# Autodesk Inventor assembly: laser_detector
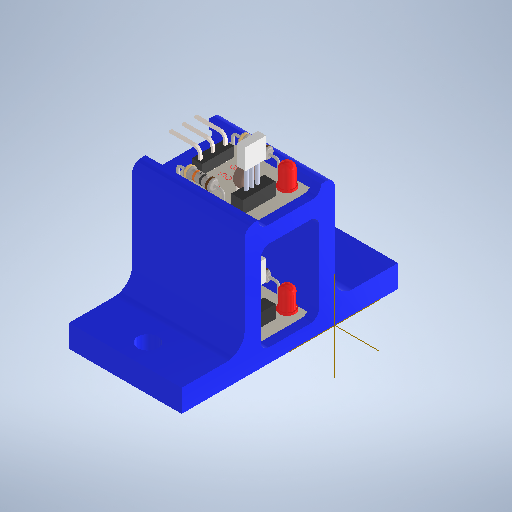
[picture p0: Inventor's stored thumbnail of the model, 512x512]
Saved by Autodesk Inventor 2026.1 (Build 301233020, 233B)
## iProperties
Created: 2026-10
Part Number: laser_detector
Document SubType Name: Assembly
Designer: alolo
Author: alolo
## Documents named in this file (3)
- C:\Users\hp\Documents\Inventor\DOM1_CartesianRobot\laser_detector.iam
- C:\Users\hp\Documents\Inventor\DOM1_CartesianRobot\Laser Detection Hardware.ipt
- C:\Users\hp\Documents\Inventor\DOM1_CartesianRobot\laser_rack.ipt
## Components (3 placed, 2 different names)
1. laser_rack:1 — Mate:1, Mate:2, Mate:3, Mate:4, Mate:5, Mate:6, Mate:7, Mate:8, Mate:9
2. Laser Detection Hardware:1 — Mate:4, Mate:5, Mate:6
3. Laser Detection Hardware:2 — Mate:7, Mate:8, Mate:9
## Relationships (9: Mate 9)
- Mate:1: laser_rack:1
- Mate:2: laser_rack:1
- Mate:3: laser_rack:1
- Mate:4: laser_rack:1 ↔ Laser Detection Hardware:1
- Mate:5: laser_rack:1 ↔ Laser Detection Hardware:1
- Mate:6: laser_rack:1 ↔ Laser Detection Hardware:1
- Mate:7: laser_rack:1 ↔ Laser Detection Hardware:2
- Mate:8: laser_rack:1 ↔ Laser Detection Hardware:2
- Mate:9: laser_rack:1 ↔ Laser Detection Hardware:2
